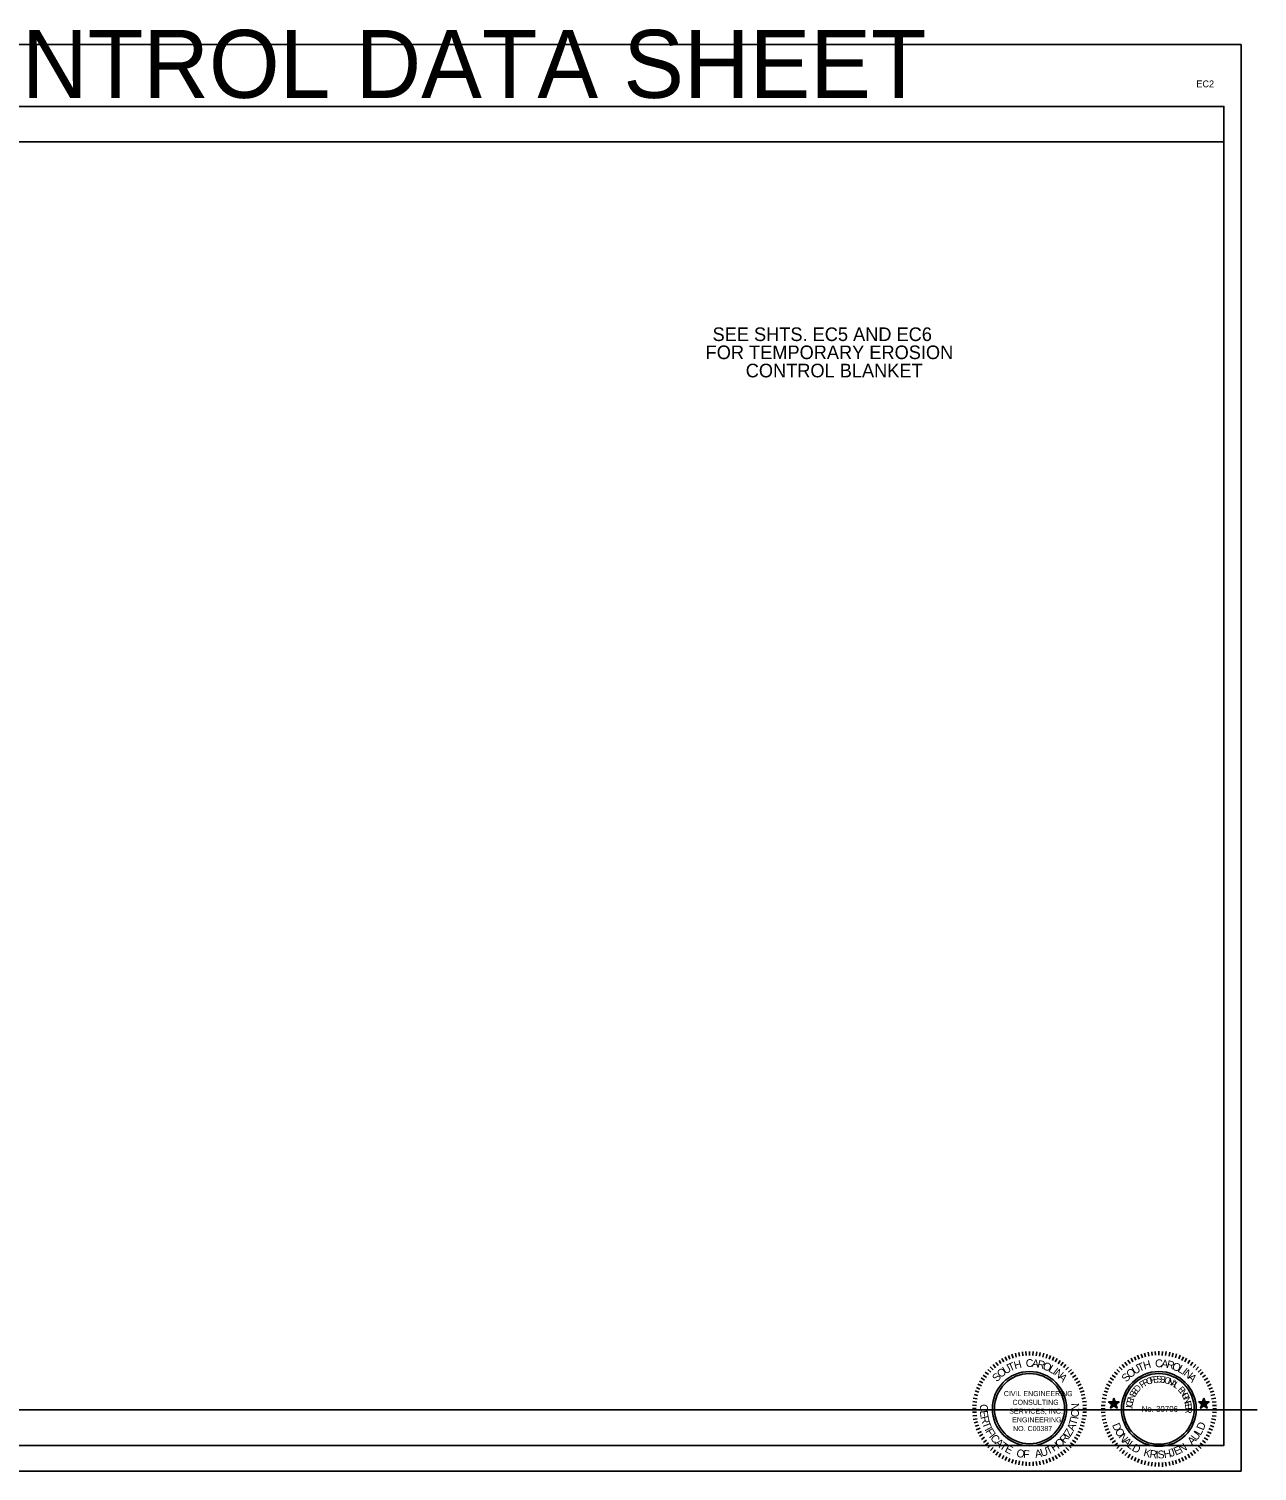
# Model space of a CAD drawing. Extents: x 260980 to 262786, y 322333 to 323393.
# Drawn here: x 261883 to 262786, y 322333 to 323393 of the extents above; entities that cross this region are included whole.
import ezdxf

# ---------------------------------------------------------------- set-up
doc = ezdxf.new("R2010")
doc.units = 0
for name, color, linetype in [('Level 2', 7, 'Continuous'), ('Level 23', 7, 'Continuous'), ('Level 3', 7, 'Continuous'), ('Level 8', 7, 'Continuous'), ('RD_SHT_SEAL_KA', 7, 'Continuous')]:
    doc.layers.add(name, color=color, linetype=linetype)

msp = doc.modelspace()

# ---------------------------------------------------------------- linework, layer by layer
at = {"layer": 'Level 2'}
msp.add_line((262762, 322377.8), (262786, 322377.8), dxfattribs=at)
at = {"layer": 'Level 23'}
msp.add_lwpolyline([(261111.1, 323336.4), (262761.5, 323336.4), (262761.5, 322351.8), (261111.1, 322351.8)], close=True, dxfattribs=at)
msp.add_lwpolyline([(261111.1, 323336.4), (262761.5, 323336.4), (262761.5, 322351.8), (261111.1, 322351.8)], close=True, dxfattribs=at)
at = {"layer": 'Level 3'}
for p, q in [((261099.2, 323381.9), (262774.2, 323381.9)), ((262774.2, 322332.8), (262774.2, 323381.9)), ((261099.2, 322332.9), (262774.2, 322332.9))]:
    msp.add_line(p, q, dxfattribs=at)
msp.add_lwpolyline([(261111.1, 322377.8), (262761.5, 322377.8), (262761.5, 323310.5), (261111.1, 323310.5)], close=True, dxfattribs=at)
at = {"layer": 'RD_SHT_SEAL_KA'}
for p, q in [((262600.7, 322416.8), (262602, 322414.2)), ((262603.2, 322417.9), (262604.2, 322415.2)), ((262605.6, 322418.8), (262606.5, 322416)), ((262608.2, 322419.5), (262608.8, 322416.7)), ((262610.8, 322420.2), (262611.3, 322417.3)), ((262613.4, 322420.5), (262613.8, 322417.7)), ((262616, 322420.8), (262616.2, 322417.9)), ((262618.7, 322420.9), (262618.7, 322418)), ((262621.3, 322420.8), (262621.1, 322417.9)), ((262623.9, 322420.5), (262623.5, 322417.7)), ((262626.5, 322420.1), (262626, 322417.4)), ((262629.1, 322419.5), (262628.4, 322416.7)), ((262631.6, 322418.8), (262630.8, 322416)), ((262634.1, 322417.9), (262633.1, 322415.2)), ((262636.5, 322416.8), (262635.4, 322414.2)), ((262693.3, 322415.8), (262694.7, 322413.2)), ((262695.7, 322417), (262696.9, 322414.4)), ((262698.1, 322418.1), (262699.2, 322415.3)), ((262700.6, 322418.9), (262701.6, 322416.2)), ((262703.1, 322419.7), (262703.9, 322416.9)), ((262705.8, 322420.3), (262706.3, 322417.4)), ((262708.5, 322420.6), (262708.8, 322417.8)), ((262711.1, 322420.9), (262711.2, 322418.1)), ((262713.8, 322421), (262713.7, 322418.2)), ((262716.3, 322420.9), (262716.2, 322417.9)), ((262719.1, 322420.7), (262718.7, 322417.8)), ((262721.7, 322420.3), (262721.2, 322417.5)), ((262724.3, 322419.7), (262723.6, 322416.9)), ((262726.8, 322419), (262726, 322416.2)), ((262729.4, 322418.1), (262728.3, 322415.4)), ((262731.8, 322417), (262730.5, 322414.3)), ((262734.1, 322415.8), (262732.8, 322413.3)), ((262586.1, 322405.6), (262588.5, 322403.8)), ((262588, 322407.5), (262590.2, 322405.6)), ((262589.8, 322409.5), (262591.9, 322407.4)), ((262591.9, 322411.3), (262593.7, 322408.9)), ((262593.9, 322412.8), (262595.5, 322410.6)), ((262596.2, 322414.3), (262597.6, 322411.9)), ((262598.3, 322415.7), (262599.7, 322413.1)), ((262638.9, 322415.7), (262637.4, 322413.2)), ((262641.2, 322414.2), (262639.6, 322411.8)), ((262643.3, 322412.9), (262641.6, 322410.5)), ((262645.4, 322411.2), (262643.7, 322409)), ((262647.4, 322409.4), (262645.4, 322407.4)), ((262649.4, 322407.6), (262647.2, 322405.6)), ((262651, 322405.6), (262648.8, 322403.8)), ((262681, 322405.6), (262683.3, 322403.8)), ((262682.8, 322407.5), (262684.9, 322405.6)), ((262684.6, 322409.5), (262686.7, 322407.4)), ((262686.7, 322411.3), (262688.5, 322409)), ((262688.8, 322412.9), (262690.5, 322410.6)), ((262691, 322414.4), (262692.6, 322412)), ((262736.5, 322414.4), (262734.9, 322412)), ((262738.7, 322412.9), (262737, 322410.5)), ((262740.8, 322411.3), (262738.9, 322409.1)), ((262742.8, 322409.5), (262740.9, 322407.4)), ((262744.7, 322407.6), (262742.6, 322405.6)), ((262746.4, 322405.6), (262744.2, 322403.8)), ((262580.6, 322396.7), (262583.2, 322395.5)), ((262581.8, 322399), (262584.2, 322397.7)), ((262583.1, 322401.4), (262585.6, 322399.8)), ((262584.6, 322403.5), (262586.9, 322401.8)), ((262652.7, 322403.5), (262650.3, 322401.8)), ((262654.2, 322401.3), (262651.7, 322399.8)), ((262655.6, 322399.1), (262653, 322397.6)), ((262656.6, 322396.7), (262654.2, 322395.5)), ((262675.3, 322396.7), (262677.9, 322395.4)), ((262676.6, 322399), (262679.1, 322397.6)), ((262677.9, 322401.4), (262680.4, 322399.8)), ((262679.4, 322403.5), (262681.8, 322401.8)), ((262748, 322403.5), (262745.7, 322401.9)), ((262749.6, 322401.3), (262747.1, 322399.8)), ((262750.9, 322399), (262748.4, 322397.6)), ((262752.1, 322396.7), (262749.5, 322395.4)), ((262576.9, 322384), (262579.8, 322383.6)), ((262577.3, 322386.6), (262580.2, 322386.1)), ((262577.9, 322389.2), (262580.7, 322388.4)), ((262578.6, 322391.8), (262581.4, 322390.9)), ((262579.6, 322394.3), (262582.1, 322393.2)), ((262657.7, 322394.3), (262655.1, 322393.2)), ((262658.7, 322391.8), (262655.9, 322390.9)), ((262659.4, 322389.2), (262656.6, 322388.6)), ((262659.9, 322386.7), (262657.1, 322386.1)), ((262660.5, 322384.1), (262657.5, 322383.7)), ((262672.1, 322386.5), (262675, 322386)), ((262672.6, 322389.1), (262675.5, 322388.4)), ((262673.4, 322391.7), (262676.1, 322390.8)), ((262674.3, 322394.2), (262677, 322393.1)), ((262753.2, 322394.2), (262750.5, 322393.2)), ((262754.1, 322391.7), (262751.4, 322390.8)), ((262754.9, 322389.2), (262752, 322388.5)), ((262755.5, 322386.6), (262752.5, 322386)), ((262576.7, 322381.3), (262579.6, 322381.2)), ((262576.7, 322378.8), (262579.5, 322378.8)), ((262576.7, 322376.1), (262579.6, 322376.3)), ((262576.9, 322373.5), (262579.8, 322373.8)), ((262660.4, 322373.5), (262657.5, 322373.8)), ((262660.6, 322381.4), (262657.7, 322381.2)), ((262660.6, 322376.1), (262657.7, 322376.3)), ((262660.6, 322378.8), (262657.9, 322378.8)), ((262671.4, 322381.2), (262674.3, 322381.1)), ((262671.4, 322378.6), (262674.2, 322378.6)), ((262671.4, 322375.9), (262674.2, 322376.1)), ((262671.7, 322383.9), (262674.5, 322383.6)), ((262671.7, 322373.2), (262674.6, 322373.7)), ((262755.8, 322373.3), (262752.9, 322373.6)), ((262755.9, 322383.9), (262753, 322383.6)), ((262756.1, 322381.2), (262753.2, 322381.1)), ((262756.1, 322376), (262753.2, 322376.2)), ((262756.2, 322378.6), (262753.3, 322378.6)), ((262577.3, 322370.9), (262580.1, 322371.4)), ((262577.9, 322368.3), (262580.6, 322369)), ((262578.7, 322365.8), (262581.4, 322366.6)), ((262579.5, 322363.2), (262582.3, 322364.4)), ((262657.7, 322363.3), (262655.1, 322364.4)), ((262658.7, 322365.8), (262655.9, 322366.6)), ((262659.4, 322368.3), (262656.6, 322369)), ((262659.9, 322370.8), (262657.1, 322371.4)), ((262672, 322370.6), (262674.8, 322371.1)), ((262672.7, 322368), (262675.4, 322368.7)), ((262673.4, 322365.5), (262676.1, 322366.4)), ((262674.2, 322363), (262677, 322364)), ((262753.2, 322363), (262750.4, 322364.1)), ((262754.1, 322365.5), (262751.4, 322366.4)), ((262754.9, 322368.1), (262752, 322368.8)), ((262755.5, 322370.6), (262752.5, 322371.2)), ((262580.6, 322360.8), (262583.3, 322362.1)), ((262581.8, 322358.5), (262584.3, 322360)), ((262583.2, 322356.2), (262585.6, 322357.8)), ((262584.7, 322353.9), (262586.9, 322355.7)), ((262586.2, 322352), (262588.4, 322353.7)), ((262651.1, 322351.9), (262648.8, 322353.7)), ((262652.7, 322353.9), (262650.3, 322355.7)), ((262654.2, 322356.1), (262651.7, 322357.7)), ((262655.5, 322358.5), (262652.9, 322359.9)), ((262656.7, 322360.9), (262654.2, 322362.1)), ((262675.4, 322360.5), (262678, 322361.8)), ((262676.5, 322358.1), (262679.1, 322359.6)), ((262678, 322355.8), (262680.3, 322357.4)), ((262679.4, 322353.6), (262681.8, 322355.4)), ((262681.1, 322351.6), (262683.3, 322353.4)), ((262746.5, 322351.6), (262744.2, 322353.4)), ((262748.1, 322353.6), (262745.7, 322355.3)), ((262749.6, 322355.8), (262747.1, 322357.3)), ((262750.9, 322358.2), (262748.4, 322359.5)), ((262752.1, 322360.5), (262749.5, 322361.8)), ((262588, 322350), (262590.2, 322351.9)), ((262589.9, 322348.1), (262591.9, 322350.2)), ((262591.9, 322346.3), (262593.6, 322348.5)), ((262593.9, 322344.7), (262595.6, 322347)), ((262596.1, 322343.2), (262597.6, 322345.7)), ((262598.4, 322341.9), (262599.8, 322344.3)), ((262600.8, 322340.6), (262601.9, 322343.4)), ((262603.2, 322339.6), (262604.2, 322342.2)), ((262605.7, 322338.7), (262606.5, 322341.5)), ((262634.1, 322339.6), (262633.1, 322342.3)), ((262636.6, 322340.7), (262635.4, 322343.3)), ((262638.9, 322341.9), (262637.6, 322344.3)), ((262641.1, 322343.3), (262639.6, 322345.6)), ((262643.3, 322344.7), (262641.7, 322347)), ((262645.4, 322346.3), (262643.7, 322348.5)), ((262647.5, 322348.1), (262645.4, 322350.2)), ((262649.3, 322350), (262647.2, 322351.9)), ((262682.8, 322349.5), (262684.9, 322351.5)), ((262684.8, 322347.6), (262686.7, 322349.7)), ((262686.7, 322345.9), (262688.5, 322348.1)), ((262688.8, 322344.3), (262690.6, 322346.6)), ((262691, 322342.7), (262692.6, 322345.2)), ((262693.3, 322341.4), (262694.7, 322343.9)), ((262695.7, 322340.2), (262696.9, 322342.8)), ((262698.1, 322339.1), (262699.3, 322341.8)), ((262729.4, 322339.1), (262728.3, 322341.8)), ((262731.9, 322340.2), (262730.6, 322342.8)), ((262734.1, 322341.4), (262732.8, 322343.9)), ((262736.5, 322342.7), (262734.9, 322345.2)), ((262738.7, 322344.3), (262737.1, 322346.6)), ((262740.7, 322345.9), (262738.9, 322348.1)), ((262742.8, 322347.6), (262740.8, 322349.8)), ((262744.7, 322349.5), (262742.6, 322351.5)), ((262608.2, 322338), (262608.8, 322340.8)), ((262610.8, 322337.4), (262611.3, 322340.3)), ((262613.4, 322336.9), (262613.8, 322339.9)), ((262616.1, 322336.7), (262616.2, 322339.7)), ((262618.7, 322336.7), (262618.7, 322339.5)), ((262621.4, 322336.7), (262621.2, 322339.7)), ((262623.9, 322337), (262623.5, 322339.9)), ((262626.4, 322337.4), (262626, 322340.2)), ((262629.1, 322338), (262628.4, 322340.8)), ((262631.6, 322338.7), (262630.8, 322341.4)), ((262700.7, 322338.2), (262701.5, 322341)), ((262703.2, 322337.4), (262703.8, 322340.3)), ((262705.8, 322336.9), (262706.3, 322339.8)), ((262708.4, 322336.5), (262708.8, 322339.4)), ((262711.1, 322336.2), (262711.3, 322339.1)), ((262713.8, 322336.2), (262713.8, 322339.1)), ((262716.4, 322336.1), (262716.3, 322339.2)), ((262719, 322336.5), (262718.7, 322339.4)), ((262721.7, 322336.9), (262721.2, 322339.8)), ((262724.3, 322337.5), (262723.7, 322340.3)), ((262726.8, 322338.2), (262726, 322340.9))]:
    msp.add_line(p, q, dxfattribs=at)
for points in [[(262680.7, 322386.5), (262679.8, 322383.7), (262676.8, 322383.7), (262679.2, 322381.9), (262678.2, 322379.2), (262680.7, 322380.9), (262683.1, 322379.2), (262682.1, 322381.9), (262684.5, 322383.7), (262681.6, 322383.7)], [(262680.6, 322386.1), (262679.9, 322383.6), (262677.2, 322383.6), (262679.3, 322382), (262678.5, 322379.4), (262680.6, 322381.1), (262682.8, 322379.4), (262682, 322382), (262684.2, 322383.6), (262681.5, 322383.6)], [(262680.7, 322385.7), (262679.9, 322383.4), (262677.5, 322383.4), (262679.5, 322382), (262678.8, 322379.8), (262680.7, 322381.2), (262682.6, 322379.7), (262681.8, 322382.1), (262683.8, 322383.4), (262681.4, 322383.4)], [(262680.7, 322385.3), (262680, 322383.3), (262677.9, 322383.3), (262679.6, 322382.1), (262679, 322380.1), (262680.6, 322381.3), (262682.4, 322380.1), (262681.8, 322382.1), (262683.4, 322383.4), (262681.3, 322383.3)], [(262680.7, 322385), (262680.1, 322383.2), (262678.3, 322383.2), (262679.8, 322382.1), (262679.2, 322380.4), (262680.7, 322381.5), (262682.2, 322380.4), (262681.6, 322382.1), (262683, 322383.2), (262681.3, 322383.2)], [(262680.7, 322384.6), (262680.2, 322383.1), (262678.7, 322383.1), (262679.9, 322382.2), (262679.4, 322380.7), (262680.7, 322381.7), (262682, 322380.7), (262681.4, 322382.2), (262682.7, 322383), (262681.2, 322383.1)], [(262680.7, 322384.1), (262680.3, 322383), (262679.1, 322382.8), (262680.1, 322382.3), (262679.7, 322381.1), (262680.6, 322381.8), (262681.8, 322381), (262681.4, 322382.3), (262682.3, 322383), (262681.1, 322383)], [(262746.8, 322386.5), (262745.9, 322383.7), (262743, 322383.7), (262745.4, 322381.9), (262744.4, 322379.1), (262746.8, 322380.9), (262749.2, 322379.1), (262748.2, 322381.9), (262750.7, 322383.7), (262747.7, 322383.7)], [(262746.8, 322386.1), (262746, 322383.6), (262743.3, 322383.6), (262745.5, 322381.9), (262744.7, 322379.4), (262746.8, 322381), (262749, 322379.4), (262748.2, 322382), (262750.3, 322383.6), (262747.6, 322383.6)], [(262746.8, 322385.7), (262746.1, 322383.4), (262743.7, 322383.4), (262745.6, 322382), (262744.9, 322379.7), (262746.8, 322381.2), (262748.8, 322379.8), (262748, 322382), (262750, 322383.5), (262747.6, 322383.4)], [(262746.8, 322385.3), (262746.2, 322383.3), (262744.1, 322383.3), (262745.9, 322382.1), (262745, 322380.1), (262746.8, 322381.3), (262748.5, 322380.1), (262747.9, 322382.1), (262749.6, 322383.3), (262747.5, 322383.3)], [(262746.8, 322384.9), (262746.2, 322383.2), (262744.4, 322383.2), (262745.9, 322382.2), (262745.4, 322380.4), (262746.8, 322381.4), (262748.2, 322380.4), (262747.7, 322382.1), (262749.3, 322383.2), (262747.4, 322383.2)], [(262746.9, 322384.5), (262746.3, 322383.1), (262744.8, 322383.1), (262746.1, 322382.3), (262745.5, 322380.7), (262746.8, 322381.6), (262748, 322380.7), (262747.6, 322382.1), (262748.8, 322383.1), (262747.3, 322383.1)], [(262746.8, 322384.1), (262746.4, 322383), (262745.2, 322383), (262746.2, 322382.2), (262745.8, 322381.1), (262746.8, 322381.8), (262747.8, 322381), (262747.4, 322382.3), (262748.5, 322383), (262747.2, 322383)], [(262680.7, 322383.8), (262680.4, 322382.8), (262679.4, 322382.8), (262680.2, 322382.3), (262679.9, 322381.4), (262680.7, 322381.9), (262681.5, 322381.3), (262681.2, 322382.3), (262682, 322382.8), (262680.9, 322382.9)], [(262680.7, 322383.3), (262680.5, 322382.7), (262679.8, 322382.7), (262680.3, 322382.3), (262680.2, 322381.7), (262680.7, 322382.1), (262681.2, 322381.7), (262681.1, 322382.3), (262681.6, 322382.7), (262680.9, 322382.7)], [(262680.7, 322383), (262680.5, 322382.6), (262680.2, 322382.6), (262680.5, 322382.4), (262680.4, 322382), (262680.7, 322382.3), (262680.9, 322382), (262680.8, 322382.4), (262681.2, 322382.6), (262680.8, 322382.6)], [(262680.7, 322382.6), (262680.7, 322382.4), (262680.5, 322382.5), (262680.6, 322382.5), (262680.6, 322382.3), (262680.7, 322382.3), (262680.7, 322382.3), (262680.7, 322382.4), (262680.9, 322382.5), (262680.7, 322382.5)], [(262746.8, 322383.7), (262746.6, 322382.8), (262745.5, 322382.8), (262746.3, 322382.3), (262746, 322381.4), (262746.8, 322381.9), (262747.6, 322381.3), (262747.3, 322382.3), (262748, 322382.8), (262747.1, 322382.8)], [(262746.8, 322383.4), (262746.5, 322382.7), (262746, 322382.7), (262746.4, 322382.4), (262746.2, 322381.7), (262746.8, 322382), (262747.4, 322381.7), (262747.1, 322382.3), (262747.7, 322382.7), (262747.1, 322382.7)], [(262746.8, 322383), (262746.7, 322382.6), (262746.3, 322382.6), (262746.7, 322382.4), (262746.4, 322382), (262746.9, 322382.2), (262747.1, 322382), (262747, 322382.3), (262747.4, 322382.6), (262747, 322382.6)], [(262746.9, 322382.6), (262746.8, 322382.5), (262746.7, 322382.5), (262746.7, 322382.4), (262746.7, 322382.3), (262746.8, 322382.4), (262746.9, 322382.4), (262746.9, 322382.4), (262746.9, 322382.5), (262746.8, 322382.4)]]:
    msp.add_lwpolyline(points, close=True, dxfattribs=at)
for radius in [27.5, 26]:
    msp.add_circle((262713.7, 322378.6), radius, dxfattribs=at)
for major_axis in [(0, 27.3), (0, 25.8)]:
    msp.add_ellipse((262618.6, 322378.8), major_axis=major_axis, ratio=0.998589, dxfattribs=at)

# ---------------------------------------------------------------- texts
at = {"layer": 'Level 3'}
for s, height, p in [('EC2', 5, (262741.3, 323350.5)), ('SEE SHTS. EC5 AND EC6', 10, (262385.6, 323163.9)), ('FOR TEMPORARY EROSION', 10, (262380.5, 323150.6)), ('CONTROL BLANKET', 10, (262410, 323137.2))]:
    msp.add_text(s, height=height, dxfattribs=at).set_placement(p)
at = {"layer": 'Level 8'}
msp.add_text('EROSION CONTROL DATA SHEET', height=50, dxfattribs=at).set_placement((261450.7, 323342.7))
at = {"layer": 'RD_SHT_SEAL_KA'}
for s, height, rotation, p in [('O', 5.79, 39.0332, (262597.5, 322401.1)), ('U', 5.79, 30.8031, (262600.9, 322403.9)), ('T', 5.79, 23.2887, (262604.3, 322406)), ('H', 5.79, 15.7743, (262608, 322407.6)), ('C', 5.79, 0.6858, (262615.9, 322409.4)), ('A', 5.79, 352.8136, (262620.1, 322409.5)), ('R', 5.79, 345.657, (262623.9, 322409.1)), ('O', 5.79, 338.1426, (262627.8, 322408.1)), ('L', 5.79, 329.9125, (262632, 322406.5)), ('I', 5.79, 323.1138, (262635.1, 322404.7)), ('N', 5.79, 320.609, (262636.3, 322404)), ('O', 5.79, 39.0332, (262692.6, 322400.9)), ('U', 5.79, 30.8031, (262696, 322403.7)), ('T', 5.79, 23.2887, (262699.4, 322405.8)), ('H', 5.79, 15.7743, (262703.1, 322407.5)), ('C', 5.79, 0.6858, (262711, 322409.2)), ('A', 5.79, 352.8136, (262715.2, 322409.3)), ('R', 5.79, 345.657, (262719, 322408.9)), ('O', 5.79, 338.1426, (262722.9, 322407.9)), ('L', 5.79, 329.9125, (262727.1, 322406.3)), ('I', 5.79, 323.1138, (262730.2, 322404.6)), ('N', 5.79, 320.609, (262731.4, 322403.8)), ('S', 5.79, 46.5476, (262594.7, 322398.1)), ('A', 5.79, 313.0946, (262639.4, 322401.5)), ('S', 5.79, 46.5476, (262689.8, 322397.9)), ('D', 4.82, 48.9361, (262698.2, 322390.4)), ('P', 4.82, 35.3308, (262701.4, 322393.7)), ('R', 4.82, 28.555, (262703.3, 322395)), ('O', 4.82, 21.7793, (262705.3, 322396.1)), ('F', 4.82, 14.3582, (262707.6, 322397.1)), ('E', 4.82, 7.9051, (262709.8, 322397.6)), ('S', 4.82, 1.452, (262711.9, 322398)), ('S', 4.82, 354.6762, (262714.2, 322398)), ('I', 4.82, 347.9004, (262716.5, 322397.8)), ('O', 4.82, 345.6418, (262717.3, 322397.7)), ('N', 4.82, 338.2207, (262719.7, 322397.1)), ('A', 4.82, 331.445, (262721.9, 322396.3)), ('L', 4.82, 324.9919, (262723.8, 322395.2)), ('E', 4.82, 312.0319, (262727.3, 322392.5)), ('A', 5.79, 313.0946, (262734.5, 322401.3)), ('CIVIL ENGINEERING', 3.751, 359.9897, (262599.7, 322388)), ('CONSULTING', 3.75, 359.9897, (262606.1, 322381.6)), ('C', 4.82, 82.4923, (262694.3, 322379.8)), ('E', 4.82, 75.3939, (262694.6, 322382.2)), ('N', 4.82, 68.9407, (262695.1, 322384.3)), ('S', 4.82, 62.165, (262695.9, 322386.5)), ('E', 4.82, 55.3892, (262697, 322388.5)), ('N', 4.82, 305.5788, (262728.7, 322390.9)), ('G', 4.82, 298.803, (262730.1, 322389.1)), ('I', 4.82, 291.7046, (262731.3, 322387)), ('N', 4.82, 289.446, (262731.6, 322386.3)), ('E', 4.82, 282.6702, (262732.4, 322384.1)), ('C', 5.79, 268.515, (262582.3, 322382.2)), ('E', 5.79, 276.3872, (262582.1, 322377.2)), ('R', 5.79, 283.5438, (262582.6, 322372.7)), ('SERVICES, INC.', 3.751, 359.9897, (262603.7, 322375.1)), ('O', 5.79, 83.6128, (262654.6, 322372.2)), ('N', 5.79, 91.8428, (262655.2, 322377.4)), ('I', 4.82, 84.7509, (262694.3, 322379.1)), ('L', 4.82, 90.8813, (262694.3, 322377)), ('E', 4.82, 276.2171, (262732.9, 322382)), ('R', 4.82, 269.764, (262733.1, 322379.8)), ('T', 5.79, 291.0582, (262583.7, 322368)), ('I', 5.79, 298.5727, (262585.4, 322363.5)), ('F', 5.79, 301.0775, (262586.1, 322362.1)), ('ENGINEERING', 3.751, 359.9897, (262605.9, 322368.7)), ('NO. C00387', 3.75, 359.9897, (262606.5, 322362.3)), ('Z', 5.79, 58.9225, (262648.6, 322357.8)), ('A', 5.79, 66.437, (262651.1, 322361.9)), ('T', 5.79, 73.5935, (262652.9, 322366.1)), ('I', 5.79, 81.108, (262654.3, 322370.7)), ('D', 5.78, 292.563, (262679.2, 322366.8)), ('O', 5.78, 300.0892, (262681.1, 322362.4)), ('D', 5.78, 67.437, (262746.4, 322362.4)), ('I', 5.79, 308.234, (262588.5, 322358.2)), ('C', 5.79, 310.7388, (262589.4, 322356.9)), ('A', 5.79, 318.6111, (262592.7, 322353.1)), ('T', 5.79, 325.7677, (262596.1, 322350)), ('E', 5.79, 333.2821, (262600, 322347.3)), ('H', 5.79, 33.1588, (262636.5, 322346.9)), ('O', 5.79, 40.6733, (262640.5, 322349.5)), ('R', 5.79, 48.9033, (262644.5, 322352.9)), ('I', 5.79, 56.4177, (262647.6, 322356.5)), ('N', 5.78, 308.3321, (262683.7, 322357.9)), ('A', 5.78, 315.8583, (262686.7, 322354.1)), ('L', 5.78, 323.0261, (262690, 322351)), ('D', 5.78, 329.8355, (262693.4, 322348.3)), ('N', 5.78, 30.8215, (262730.3, 322346.1)), ('A', 5.78, 45.9336, (262738.2, 322351.6)), ('U', 5.78, 53.1014, (262741.4, 322354.8)), ('L', 5.78, 60.6276, (262744.3, 322358.7)), ('O', 5.79, 348.0127, (262608.6, 322343.6)), ('F', 5.79, 356.2428, (262613.8, 322342.6)), ('A', 5.79, 10.9734, (262623.1, 322342.5)), ('U', 5.79, 18.13, (262627.6, 322343.3)), ('T', 5.79, 25.6444, (262632.2, 322344.8)), ('K', 5.78, 344.9476, (262702, 322344.1)), ('R', 5.78, 352.4738, (262706.6, 322342.8)), ('I', 5.78, 360, (262711.4, 322342.2)), ('S', 5.78, 2.5087, (262712.9, 322342.1)), ('H', 5.78, 10.0349, (262717.7, 322342.3)), ('J', 5.78, 17.5611, (262722.4, 322343.2)), ('E', 5.78, 23.6537, (262726.1, 322344.3))]:
    msp.add_text(s, height=height, rotation=rotation, dxfattribs=at).set_placement(p)
msp.add_text('No. 30706', height=4.34, dxfattribs=at).set_placement((262701, 322376.4))

doc.saveas('drawing.dxf')
